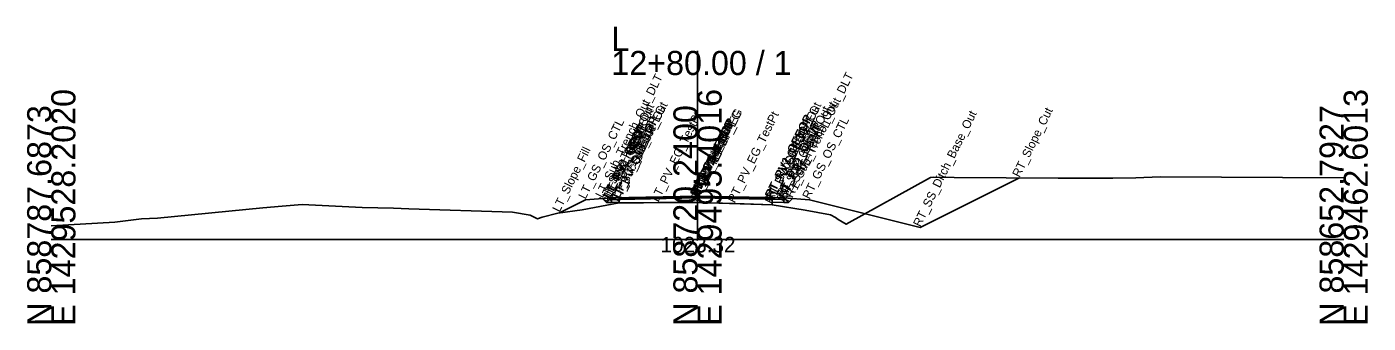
# Model space of a CAD drawing. Extents: x -26 to 2303, y -10 to 19558.
# Drawn here: x 1147.2 to 1302.8, y 4490.3 to 4524.7 of the extents above; entities that cross this region are included whole.
import ezdxf

# ---------------------------------------------------------------- set-up
doc = ezdxf.new("R2010")
doc.units = 0
for name, color, linetype in [('Default', 7, 'Continuous'), ('Exist CMT Pavement', 7, 'Continuous'), ('Exist Cross Section Cell', 7, 'Continuous'), ('Exist XS Center Line Elevation Label', 7, 'Continuous'), ('Exist XS Ground Line', 7, 'Continuous'), ('Prop CMT Pvmt Course 1', 7, 'Continuous'), ('Prop CMT Pvmt Course 1 Wedge', 7, 'Continuous'), ('Prop CMT Pvmt Course 2', 7, 'Continuous'), ('Prop CMT Pvmt Course 2 Wedge', 7, 'Continuous'), ('Prop CMT Pvmt Surface', 7, 'Continuous'), ('Prop CMT Pvmt Surface Shoulder', 7, 'Continuous'), ('Prop CMT Pvmt Wedge Surface 1', 7, 'Continuous'), ('Prop CMT Pvmt Wedge Surface 2', 7, 'Continuous'), ('Prop CMT Shld Paved Course 1', 7, 'Continuous'), ('Prop CMT Shld Paved Course 2', 7, 'Continuous'), ('Prop CMT Slope Grass', 7, 'Continuous'), ('Prop CMT Subgrade Earthwork', 7, 'Continuous'), ('Prop XS Dump Level', 7, 'Continuous')]:
    doc.layers.add(name, color=color, linetype=linetype)

msp = doc.modelspace()

# ---------------------------------------------------------------- linework, layer by layer
at = {"layer": 'Exist CMT Pavement'}
for points in [[(1225, 4504.32), (1215.89, 4504.28)], [(1215.89, 4504.28), (1220.44, 4504.3)], [(1220.44, 4504.3), (1225, 4504.32)], [(1229.33, 4504.18), (1225, 4504.32)], [(1225, 4504.32), (1233.67, 4504.05)], [(1233.67, 4504.05), (1229.33, 4504.18)]]:
    msp.add_lwpolyline(points, dxfattribs=at)
at = {"layer": 'Exist Cross Section Cell'}
for p, q in [((1225, 4500), (1225, 4521.9)), ((1150, 4500), (1225, 4500)), ((1225, 4500), (1300, 4500))]:
    msp.add_line(p, q, dxfattribs=at)
at = {"layer": 'Exist XS Ground Line'}
msp.add_lwpolyline([(1150, 4501.61), (1157.38, 4502.01), (1160.46, 4502.42), (1162.32, 4502.48), (1174.56, 4503.69), (1176.79, 4503.89), (1179.1, 4504.08), (1186.06, 4503.73), (1189.71, 4503.66), (1191.48, 4503.58), (1203.53, 4503.18), (1205.58, 4502.84), (1206.42, 4502.42), (1206.98, 4502.62), (1208.79, 4503.09), (1211.6, 4503.47), (1215.89, 4504.28), (1218.72, 4504.29), (1224.69, 4504.33), (1225, 4504.32), (1227.68, 4504.24), (1233.67, 4504.05), (1237.5, 4503.41), (1240.45, 4502.89), (1241, 4502.56), (1241.34, 4502.35), (1242.24, 4501.79), (1252.05, 4507.21), (1252.37, 4507.25), (1254.77, 4507.2), (1266.84, 4507.14), (1273.22, 4507.12), (1275.87, 4507.18), (1278.71, 4507.3), (1300, 4507.18)], dxfattribs=at)
at = {"layer": 'Prop CMT Pvmt Course 1'}
for points in [[(1225, 4505.06), (1215, 4504.86)], [(1215, 4504.86), (1215, 4504.66)], [(1215, 4504.66), (1215.89, 4504.67)], [(1215.89, 4504.76), (1225, 4504.94)], [(1215.89, 4504.67), (1215.89, 4504.76)], [(1225, 4504.86), (1225, 4505.06)], [(1225, 4505.06), (1235, 4504.86)], [(1225, 4504.86), (1225, 4505.06)], [(1225, 4504.94), (1225, 4504.86), (1225, 4504.86)], [(1233.67, 4504.77), (1225, 4504.94)], [(1225, 4504.94), (1225, 4504.86), (1225, 4504.86)], [(1233.67, 4504.68), (1233.67, 4504.77)], [(1235, 4504.66), (1233.67, 4504.68)], [(1235, 4504.86), (1235, 4504.66)]]:
    msp.add_lwpolyline(points, dxfattribs=at)
at = {"layer": 'Prop CMT Pvmt Course 1 Wedge'}
for points in [[(1225, 4504.94), (1215.89, 4504.76)], [(1225, 4504.94), (1233.67, 4504.77)]]:
    msp.add_lwpolyline(points, dxfattribs=at)
at = {"layer": 'Prop CMT Pvmt Course 2'}
for points in [[(1215.89, 4504.67), (1215, 4504.66)], [(1215, 4504.66), (1215, 4504.32)], [(1215, 4504.32), (1215.89, 4504.34)], [(1215.89, 4504.34), (1215.89, 4504.67)], [(1233.67, 4504.35), (1233.67, 4504.68)], [(1233.67, 4504.68), (1235, 4504.66)], [(1235, 4504.32), (1233.67, 4504.35)], [(1235, 4504.66), (1235, 4504.32)]]:
    msp.add_lwpolyline(points, dxfattribs=at)
at = {"layer": 'Prop CMT Pvmt Course 2 Wedge'}
for points in [[(1225, 4504.86), (1215.89, 4504.67)], [(1225, 4504.86), (1233.67, 4504.68)]]:
    msp.add_lwpolyline(points, dxfattribs=at)
at = {"layer": 'Prop CMT Pvmt Surface'}
for points in [[(1225, 4505.06), (1215, 4504.86)], [(1225, 4505.06), (1235, 4504.86)]]:
    msp.add_lwpolyline(points, dxfattribs=at)
at = {"layer": 'Prop CMT Pvmt Surface Shoulder'}
for points in [[(1215, 4504.86), (1215, 4504.86)], [(1235, 4504.86), (1235, 4504.86)]]:
    msp.add_lwpolyline(points, dxfattribs=at)
at = {"layer": 'Prop CMT Pvmt Wedge Surface 1'}
for points in [[(1215, 4504.66), (1215, 4504.86)], [(1215.89, 4504.67), (1215, 4504.66)], [(1225, 4504.94), (1215.89, 4504.76)], [(1215.89, 4504.76), (1215.89, 4504.67)], [(1225, 4504.94), (1233.67, 4504.77)], [(1233.67, 4504.77), (1233.67, 4504.68)], [(1233.67, 4504.68), (1235, 4504.66)], [(1235, 4504.66), (1235, 4504.86)]]:
    msp.add_lwpolyline(points, dxfattribs=at)
at = {"layer": 'Prop CMT Pvmt Wedge Surface 2'}
for points in [[(1225, 4504.86), (1215, 4504.66)], [(1215, 4504.66), (1215, 4504.86)], [(1225, 4504.86), (1235, 4504.66)], [(1235, 4504.66), (1235, 4504.86)]]:
    msp.add_lwpolyline(points, dxfattribs=at)
at = {"layer": 'Prop CMT Shld Paved Course 1'}
for points in [[(1215, 4504.86), (1214.79, 4504.65)], [(1214.79, 4504.65), (1215, 4504.66)], [(1215, 4504.86), (1215, 4504.86)], [(1215, 4504.66), (1215, 4504.86)], [(1235, 4504.86), (1235, 4504.86)], [(1235, 4504.86), (1235.21, 4504.65)], [(1235, 4504.66), (1235, 4504.86)], [(1235.21, 4504.65), (1235, 4504.66)]]:
    msp.add_lwpolyline(points, dxfattribs=at)
at = {"layer": 'Prop CMT Shld Paved Course 2'}
for points in [[(1214.79, 4504.65), (1214.45, 4504.31)], [(1214.45, 4504.31), (1215, 4504.32)], [(1215, 4504.66), (1214.79, 4504.65)], [(1214.79, 4504.65), (1214.79, 4504.65)], [(1215, 4504.32), (1215, 4504.66)], [(1235, 4504.66), (1235.21, 4504.65)], [(1235, 4504.32), (1235, 4504.66)], [(1235.55, 4504.31), (1235, 4504.32)], [(1235.21, 4504.65), (1235.21, 4504.65)], [(1235.21, 4504.65), (1235.55, 4504.31)]]:
    msp.add_lwpolyline(points, dxfattribs=at)
at = {"layer": 'Prop CMT Slope Grass'}
for points in [[(1235, 4504.86), (1238, 4504.62), (1250.86, 4501.41), (1262.37, 4507.16)], [(1215, 4504.86), (1212, 4504.62), (1208.99, 4503.12)]]:
    msp.add_lwpolyline(points, dxfattribs=at)
at = {"layer": 'Prop CMT Subgrade Earthwork'}
for points in [[(1214.45, 4504.31), (1213.98, 4504.78)], [(1215, 4504.32), (1214.45, 4504.31)], [(1215.89, 4504.34), (1215, 4504.32)], [(1215.89, 4504.34), (1215.9, 4504.28)], [(1233.67, 4504.35), (1233.65, 4504.05)], [(1233.67, 4504.35), (1235, 4504.32)], [(1235, 4504.32), (1235.55, 4504.31)], [(1235.55, 4504.31), (1236.02, 4504.78)]]:
    msp.add_lwpolyline(points, dxfattribs=at)

# ---------------------------------------------------------------- texts
at = {"layer": 'Default'}
msp.add_text('-', height=0.0001, dxfattribs=at).set_placement((1150, 4500))
at = {"layer": 'Exist Cross Section Cell'}
for s, p in [('L', (1215, 4521.9)), ('12+80.00 / 1', (1215, 4519.1))]:
    msp.add_text(s, height=2.8, dxfattribs=at).set_placement(p)
for s, p in [('E 1429528.2020', (1152.8, 4490)), ('E 1429495.4016', (1227.8, 4490)), ('E 1429462.6013', (1302.8, 4490)), ('N 858787.6873', (1150, 4490)), ('N 858720.2400', (1225, 4490)), ('N 858652.7927', (1300, 4490))]:
    msp.add_text(s, height=2.8, rotation=90, dxfattribs=at).set_placement(p)
at = {"layer": 'Exist XS Center Line Elevation Label'}
msp.add_text('1023.32', height=1.8, dxfattribs=at).set_placement((1220.71, 4498.52))
at = {"layer": 'Prop XS Dump Level'}
for s, p in [('RT_Sub_Trench_Out_DLT', (1236.02, 4504.78)), ('LT_Sub_Trench_Out_DLT', (1213.98, 4504.78)), ('LT_Sub_Trench_Out', (1214.45, 4504.31)), ('LT_PS2_Shelf_Out', (1214.79, 4504.65)), ('LT_PV_OEEOP_EG', (1215.89, 4504.28)), ('LT_PV_Sub_Tie_Out', (1215.9, 4504.28)), ('LT_PV_EG_TestPt', (1220.44, 4504.3)), ('RT_PV_IEEOP_EG', (1225, 4504.32)), ('LT_PV_IEEOP_EG', (1225, 4504.32)), ('RT_PV_EG_TestPt', (1229.33, 4504.18)), ('RT_PV_Sub_Tie_Out', (1233.65, 4504.05)), ('RT_PV_OEEOP_EG', (1233.67, 4504.05)), ('RT_PS2_Shelf_Out', (1235.21, 4504.65)), ('RT_Sub_Trench_Out', (1235.55, 4504.31)), ('RT_SS_Ditch_Base_Out', (1250.86, 4501.41)), ('RT_Slope_Cut', (1262.37, 4507.16)), ('LT_GS_OS_CTL', (1212, 4504.62)), ('LT_PS2_OEOP', (1214.79, 4504.65)), ('LT_PV1_OEOT', (1215, 4504.86)), ('LT_PS1_OEOP', (1215, 4504.86)), ('LT_PV2_OEOT', (1215, 4504.66)), ('LT_PV1_OEEOP', (1215.89, 4504.76)), ('LT_PV2_OEEOP', (1215.89, 4504.67)), ('LT_Sub_OEEOP', (1215.89, 4504.34)), ('RT_PV1_IEEOP', (1225, 4504.94)), ('RT_PV2_IEEOP', (1225, 4504.86)), ('LT_PV1_IEEOP', (1225, 4504.94)), ('LT_PV2_IEEOP', (1225, 4504.86)), ('RT_PV1_OEEOP', (1233.67, 4504.77)), ('RT_PV2_OEEOP', (1233.67, 4504.68)), ('RT_Sub_OEEOP', (1233.67, 4504.35)), ('RT_PV1_OEOT', (1235, 4504.86)), ('RT_PS1_OEOP', (1235, 4504.86)), ('RT_PV2_OEOT', (1235, 4504.66)), ('RT_PS2_OEOP', (1235.21, 4504.65)), ('RT_GS_OS_CTL', (1238, 4504.62)), ('LT_Sub_OEOT', (1215, 4504.32)), ('RT_Sub_OEOT', (1235, 4504.32)), ('LT_Slope_Fill', (1208.99, 4503.12)), ('PV1_PGL', (1225, 4505.06)), ('PV2_PGL', (1225, 4504.86))]:
    msp.add_text(s, height=1, rotation=63.5833, dxfattribs=at).set_placement(p)

doc.saveas('drawing.dxf')
